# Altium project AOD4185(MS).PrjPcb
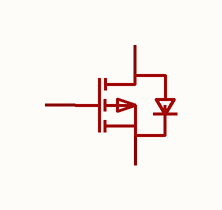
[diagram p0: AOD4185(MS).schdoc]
1 sheet, 1 parts. Net scope: global (net labels, ports and power ports of the same name join across sheets).

## Sheet AOD4185(MS).schdoc
size 127 x 101 mm

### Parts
Q?  aod4185(ms)  [TO-252-2_L6.6-W6.1-P4.60-LS10.0-BR-CW]  (value not drawn)

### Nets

Not connected (* = marked no-connect by the designer): Q? 1(G) 2(D) 3(S)

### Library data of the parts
Q? = aod4185(ms): 数量:1个P沟道;漏源电压(Vdss):40V;连续漏极电流(Id):40A;导通电阻(RDS(on)):15mΩ@10V;耗散功率(Pd):62W;阈值电压(Vgs(th)):2.5V;; Manufacturer: MSKSEMI(美森科); AddInBom: yes; ModelId: 2bfbfbb77002446c96d8a76a432e0188; ModelTransform: 246.80147,383.8575,0,90,0,0,-31.302,0.003,0; Number: 1个P沟道; Drain to Source Voltage: 40V; Current - Continuous Drain(Id): 40A; Pd - Power Dissipation: 62W; Gate Threshold Voltage (Vgs(th)): 2.5V; Gate Charge(Qg): 22.2nC@4.5V; Input Capacitance(Ciss): 2.757nF; Reverse Transfer Capacitance (Crss@Vds): 137pF; Type: P沟道; Output Capacitance(Coss): 240pF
